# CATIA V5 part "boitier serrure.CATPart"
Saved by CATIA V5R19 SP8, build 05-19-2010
Part number: boitier serrure
Revision: ANY
Definition: UNKNOWN
Nomenclature: boitier serrure
Source: Unknown
Bounding box of the stored display mesh (mm): x 0 to 163, y 0 to 77, z -1 to 7.5
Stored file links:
  D:\Documents\1_Travail\1 - ac-limoges.fr\ac-limoges.fr\Emmanuel Maynard - STI2D_Turgot\2 -2I2D\2_SEQUENCE_Serrure_Biométrique\5-Spé_ITEC\Serrure_Bio_Eleve\boitier serrure.CATPart
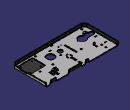
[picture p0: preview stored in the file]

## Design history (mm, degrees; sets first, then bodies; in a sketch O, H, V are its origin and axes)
Body1 "Enlèv. mat.-Extru.30" (main body)
  Solid1: solid without history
